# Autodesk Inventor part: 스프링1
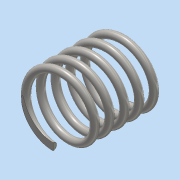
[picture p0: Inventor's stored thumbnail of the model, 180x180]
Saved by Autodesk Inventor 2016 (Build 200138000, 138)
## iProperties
Created: 2019-11
Part Number: 스프링1
Material: 스테인레스 스틸
Document SubType Name: Modeling
Designer: user
Density: 8 g/cm^3
Appearance: 반연마
Mass: 6.57252 g
Surface Area: 16.7217 cm^2
Volume: 0.821565 cm^3
Author: user
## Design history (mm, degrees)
sketch "스케치1"
  geometry: L1 (0, 0)-(20.5, 0); L2 (20.5, 0)-(20.5, -8.5); L3 (20.5, -8.5)-(0, -8.5); L4 (0, -8.5)-(0, 0); C1 r 1 at (0, -8.5)
  constraints: 8 end point, 2 parallel, 1 centre point, 1 coincident, 1 horizontal, 1 perpendicular
  dimensions: "d0" = 20.5 distance of L1.start L1.end (derived); "d1" = 17 diameter of L3 L1; "d2" = 2 diameter of C1
feature "코일1" sketch "스케치1" pitch "d3" = 10; turns "d5" = 5; dims "d4" = 20.5 (= d0), "d6" = 0, angle "d7" = 90 deg, angle "d8" = 90 deg, "d9" = 0, "d10" = 0
sketch "스케치2"
  geometry: L1 (-15.996, 0)-(15.996, 0); L2 (15.996, 0)-(15.996, 20.5); L3 (15.996, 20.5)-(-15.996, 20.5); L4 (-15.996, 20.5)-(-15.996, 0); 2 further points
  constraints: 8 end point, 2 parallel, 1 coincident, 1 horizontal, 1 midpoint, 1 perpendicular
  dimensions: "d12" = 31.99189 distance between parallel lines of L2 L4; "d13" = 20.5 distance of L1.end L2.end (= d0)
extrude "돌출1" sketch "스케치2" stored distance "d14" = 38.25; taper "d15" = 0 deg
node "솔리드1"
